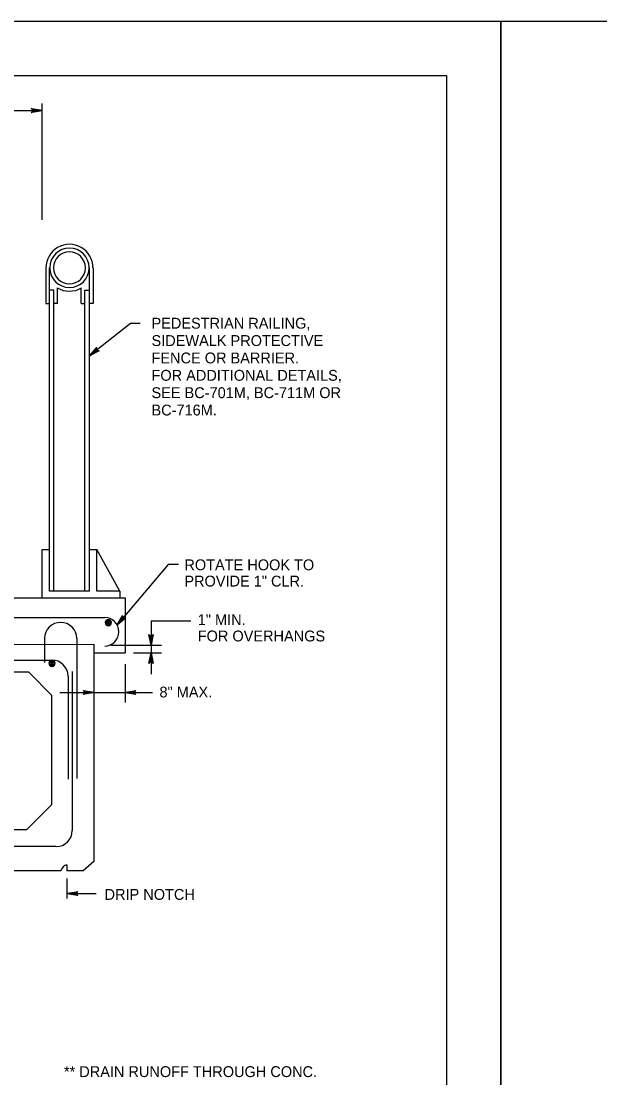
# Model space of a CAD drawing. Extents: x 639331 to 643089, y 299088 to 300975.
# Drawn here: x 642101.4 to 642261.4, y 300577.6 to 300869.7 of the extents above; entities that cross this region are included whole.
import ezdxf

# ---------------------------------------------------------------- set-up
doc = ezdxf.new("R2010")
doc.units = 0
doc.layers.add('1', color=7, linetype='Continuous')
doc.layers.add('PLT-BNDY', color=7, linetype='Continuous')

msp = doc.modelspace()

# ---------------------------------------------------------------- linework, layer by layer
at = {"layer": '1'}
for p, q in [((641433.06, 300854.66), (642219.06, 300854.66)), ((642219.06, 300854.66), (642219.06, 300290.66)), ((642107.24, 300814.74), (642107.24, 300846.94)), ((641973.91, 300844.92), (642107.24, 300844.92)), ((642108.26, 300801.46), (642108.26, 300791.65)), ((642109.28, 300712.15), (642109.28, 300801.46)), ((642120.32, 300712.15), (642120.32, 300801.46)), ((642121.34, 300801.46), (642121.34, 300791.65)), ((642110.51, 300795.33), (642109.28, 300795.33)), ((642110.51, 300712.15), (642110.51, 300795.33)), ((642111.53, 300791.65), (642111.53, 300795.95)), ((642118.07, 300791.65), (642118.07, 300795.95)), ((642119.09, 300795.33), (642120.12, 300795.33)), ((642119.09, 300712.15), (642119.09, 300795.33)), ((642108.26, 300791.65), (642109.28, 300791.65)), ((642111.53, 300791.65), (642110.51, 300791.65)), ((642118.07, 300791.65), (642119.09, 300791.65)), ((642121.34, 300791.65), (642120.32, 300791.65)), ((642131.72, 300786.07), (642120.32, 300777.19)), ((642134.31, 300786.07), (642131.72, 300786.07)), ((642107.24, 300710.31), (642107.24, 300723.6)), ((642107.24, 300723.6), (642109.28, 300723.6)), ((642120.32, 300723.6), (642122.36, 300723.6)), ((642128.7, 300712.15), (642122.36, 300723.6)), ((642122.36, 300712.15), (642122.36, 300723.6)), ((642142.1, 300719.45), (642127.99, 300702.77)), ((642144.97, 300719.45), (642142.1, 300719.45)), ((641973.91, 300710.31), (642130.2, 300710.31)), ((642107.24, 300712.15), (642107.24, 300712.15)), ((642109.28, 300712.15), (642109.28, 300712.15)), ((642120.32, 300712.15), (642109.28, 300712.15)), ((642128.7, 300712.15), (642122.36, 300712.15)), ((642128.7, 300712.15), (642122.36, 300712.15)), ((642128.7, 300712.15), (642128.7, 300710.31)), ((642130.2, 300710.31), (642130.2, 300695.12)), ((641894.89, 300704.84), (642124.52, 300704.84)), ((642137.35, 300703.88), (642137.35, 300697.19)), ((642137.35, 300703.88), (642148.38, 300703.88)), ((642107.92, 300699.03), (642107.91, 300692.42)), ((642116.83, 300699.03), (642116.83, 300660.32)), ((642011.2, 300697.32), (642121.58, 300697.43)), ((642121.58, 300697.43), (642121.58, 300637.44)), ((642121.58, 300695.11), (642130.2, 300695.12)), ((642126.27, 300697.19), (642140.28, 300697.19)), ((642132.51, 300695.12), (642140.28, 300695.12)), ((642137.35, 300697.19), (642137.35, 300695.12)), ((642137.35, 300695.12), (642137.35, 300689.18)), ((642021.7, 300693.08), (642109.95, 300693.08)), ((642110.4, 300692.17), (642110.4, 300692.17)), ((642103.57, 300689.69), (642028.08, 300689.69)), ((642109.95, 300683.32), (642103.57, 300689.69)), ((642115.58, 300689.94), (642115.58, 300645.94)), ((642130.2, 300691.94), (642130.2, 300681.38)), ((642114.41, 300688.62), (642114.41, 300660.19)), ((642112.12, 300684.11), (642121.58, 300684.11)), ((642121.58, 300684.11), (642130.2, 300684.11)), ((642130.2, 300684.11), (642137.74, 300684.11)), ((642109.95, 300653.19), (642109.95, 300683.32)), ((642109.95, 300653.19), (642102.95, 300646.19)), ((642102.95, 300646.19), (642028.83, 300646.19)), ((642111.08, 300641.57), (642020.58, 300641.57)), ((642121.58, 300637.44), (642118.58, 300634.82)), ((642112.45, 300634.82), (642013.2, 300634.82)), ((642114.08, 300636.44), (642114.08, 300634.82)), ((642118.58, 300634.82), (642114.08, 300634.82)), ((642114.12, 300632.75), (642114.12, 300627.18)), ((642114.12, 300628.54), (642122.2, 300628.54))]:
    msp.add_line(p, q, dxfattribs=at)
for points in [[(642107.24, 300844.92), (642104.26, 300844.37), (642104.37, 300844.44), (642104.49, 300844.52), (642104.55, 300844.62), (642104.61, 300844.72), (642104.62, 300844.82), (642104.64, 300844.92), (642104.62, 300845.02), (642104.61, 300845.12), (642104.55, 300845.22), (642104.49, 300845.32), (642104.37, 300845.4), (642104.26, 300845.48), (642107.24, 300844.92), (642104.37, 300845.4), (642104.49, 300845.32), (642107.24, 300844.92), (642104.55, 300845.22), (642104.61, 300845.12), (642107.24, 300844.92), (642104.62, 300845.02), (642104.64, 300844.92), (642107.24, 300844.92), (642104.62, 300844.82), (642104.61, 300844.72), (642107.24, 300844.92), (642104.55, 300844.62), (642104.49, 300844.52), (642107.24, 300844.92), (642104.37, 300844.44)], [(642120.32, 300777.19), (642122.33, 300779.47), (642122.29, 300779.33), (642122.25, 300779.2), (642122.26, 300779.09), (642122.28, 300778.97), (642122.32, 300778.88), (642122.37, 300778.79), (642122.45, 300778.72), (642122.52, 300778.65), (642122.63, 300778.61), (642122.74, 300778.57), (642122.88, 300778.58), (642123.02, 300778.58), (642120.32, 300777.19), (642122.88, 300778.58), (642122.74, 300778.57), (642120.32, 300777.19), (642122.63, 300778.61), (642122.52, 300778.65), (642120.32, 300777.19), (642122.45, 300778.72), (642122.37, 300778.79), (642120.32, 300777.19), (642122.32, 300778.88), (642122.28, 300778.97), (642120.32, 300777.19), (642122.26, 300779.09), (642122.25, 300779.2), (642120.32, 300777.19), (642122.29, 300779.33)], [(642127.99, 300702.77), (642129.49, 300705.41), (642129.48, 300705.27), (642129.46, 300705.13), (642129.5, 300705.02), (642129.54, 300704.91), (642129.6, 300704.83), (642129.67, 300704.75), (642129.76, 300704.7), (642129.84, 300704.65), (642129.96, 300704.63), (642130.07, 300704.61), (642130.21, 300704.65), (642130.34, 300704.68), (642127.99, 300702.77), (642130.21, 300704.65), (642130.07, 300704.61), (642127.99, 300702.77), (642129.96, 300704.63), (642129.84, 300704.65), (642127.99, 300702.77), (642129.76, 300704.7), (642129.67, 300704.75), (642127.99, 300702.77), (642129.6, 300704.83), (642129.54, 300704.91), (642127.99, 300702.77), (642129.5, 300705.02), (642129.46, 300705.13), (642127.99, 300702.77), (642129.48, 300705.27)], [(642137.35, 300697.19), (642136.79, 300700.17), (642136.87, 300700.06), (642136.95, 300699.94), (642137.05, 300699.89), (642137.15, 300699.83), (642137.25, 300699.81), (642137.35, 300699.79), (642137.45, 300699.81), (642137.55, 300699.83), (642137.65, 300699.89), (642137.75, 300699.94), (642137.83, 300700.06), (642137.91, 300700.17), (642137.35, 300697.19), (642137.83, 300700.06), (642137.75, 300699.94), (642137.35, 300697.19), (642137.65, 300699.89), (642137.55, 300699.83), (642137.35, 300697.19), (642137.45, 300699.81), (642137.35, 300699.79), (642137.35, 300697.19), (642137.25, 300699.81), (642137.15, 300699.83), (642137.35, 300697.19), (642137.05, 300699.89), (642136.95, 300699.94), (642137.35, 300697.19), (642136.87, 300700.06)], [(642137.35, 300695.12), (642137.91, 300692.14), (642137.83, 300692.25), (642137.75, 300692.37), (642137.65, 300692.43), (642137.55, 300692.49), (642137.45, 300692.5), (642137.35, 300692.52), (642137.25, 300692.5), (642137.15, 300692.49), (642137.05, 300692.43), (642136.95, 300692.37), (642136.87, 300692.25), (642136.79, 300692.14), (642137.35, 300695.12), (642136.87, 300692.25), (642136.95, 300692.37), (642137.35, 300695.12), (642137.05, 300692.43), (642137.15, 300692.49), (642137.35, 300695.12), (642137.25, 300692.5), (642137.35, 300692.52), (642137.35, 300695.12), (642137.45, 300692.5), (642137.55, 300692.49), (642137.35, 300695.12), (642137.65, 300692.43), (642137.75, 300692.37), (642137.35, 300695.12), (642137.83, 300692.25)], [(642121.58, 300684.11), (642118.59, 300683.55), (642118.71, 300683.63), (642118.82, 300683.71), (642118.88, 300683.81), (642118.94, 300683.91), (642118.96, 300684.01), (642118.98, 300684.11), (642118.96, 300684.21), (642118.94, 300684.31), (642118.88, 300684.41), (642118.82, 300684.51), (642118.71, 300684.59), (642118.59, 300684.67), (642121.58, 300684.11), (642118.71, 300684.59), (642118.82, 300684.51), (642121.58, 300684.11), (642118.88, 300684.41), (642118.94, 300684.31), (642121.58, 300684.11), (642118.96, 300684.21), (642118.98, 300684.11), (642121.58, 300684.11), (642118.96, 300684.01), (642118.94, 300683.91), (642121.58, 300684.11), (642118.88, 300683.81), (642118.82, 300683.71), (642121.58, 300684.11), (642118.71, 300683.63)], [(642130.2, 300684.11), (642133.18, 300684.67), (642133.07, 300684.59), (642132.95, 300684.51), (642132.89, 300684.41), (642132.84, 300684.31), (642132.82, 300684.21), (642132.8, 300684.11), (642132.82, 300684.01), (642132.84, 300683.91), (642132.89, 300683.81), (642132.95, 300683.71), (642133.07, 300683.63), (642133.18, 300683.55), (642130.2, 300684.11), (642133.07, 300683.63), (642132.95, 300683.71), (642130.2, 300684.11), (642132.89, 300683.81), (642132.84, 300683.91), (642130.2, 300684.11), (642132.82, 300684.01), (642132.8, 300684.11), (642130.2, 300684.11), (642132.82, 300684.21), (642132.84, 300684.31), (642130.2, 300684.11), (642132.89, 300684.41), (642132.95, 300684.51), (642130.2, 300684.11), (642133.07, 300684.59)], [(642114.12, 300628.54), (642117.1, 300629.1), (642116.99, 300629.02), (642116.87, 300628.94), (642116.81, 300628.84), (642116.75, 300628.74), (642116.74, 300628.64), (642116.72, 300628.54), (642116.74, 300628.44), (642116.75, 300628.34), (642116.81, 300628.24), (642116.87, 300628.14), (642116.99, 300628.06), (642117.1, 300627.98), (642114.12, 300628.54), (642116.99, 300628.06), (642116.87, 300628.14), (642114.12, 300628.54), (642116.81, 300628.24), (642116.75, 300628.34), (642114.12, 300628.54), (642116.74, 300628.44), (642116.72, 300628.54), (642114.12, 300628.54), (642116.74, 300628.64), (642116.75, 300628.74), (642114.12, 300628.54), (642116.81, 300628.84), (642116.87, 300628.94), (642114.12, 300628.54), (642116.99, 300629.02)]]:
    msp.add_lwpolyline(points, dxfattribs=at)
for centre, radius, start, end in [((642114.79, 300801.51), 6.49, 359.8169, 180.1831), ((642114.8, 300801.49), 5.45, 0, 180), ((642114.8, 300801.49), 4.41, 0, 180), ((642114.8, 300801.49), 5.45, 180, 0), ((642114.8, 300801.49), 4.41, 180, 0), ((642114.79, 300801.51), 6.49, 238.7471, 301.3782), ((642124.52, 300700.9), 3.94, 270.7157, 90), ((642125.56, 300703.44), 0.861, 0, 180), ((642125.56, 300703.44), 0.614, 0, 180), ((642112.37, 300699.03), 4.46, 90, 180), ((642112.37, 300699.03), 4.46, 0, 90), ((642125.56, 300703.44), 0.861, 180, 0), ((642125.56, 300703.44), 0.614, 180, 0), ((642125.56, 300703.44), 0.336, 0, 180), ((642125.56, 300703.44), 0.336, 180, 0), ((642125.56, 300703.44), 0.17, 0, 180), ((642125.56, 300703.44), 0.17, 180, 0), ((642125.56, 300703.44), 0.0726, 0, 180), ((642125.56, 300703.44), 0.0726, 180, 0), ((642109.95, 300692.2), 0.861, 0, 180), ((642109.95, 300692.2), 0.861, 180, 0), ((642109.95, 300692.2), 0.614, 0, 180), ((642109.95, 300692.2), 0.614, 180, 0), ((642109.95, 300692.2), 0.336, 0, 180), ((642109.95, 300692.2), 0.336, 180, 0), ((642109.95, 300692.2), 0.17, 0, 180), ((642109.95, 300692.2), 0.17, 180, 0), ((642109.95, 300692.2), 0.0726, 0, 180), ((642109.95, 300692.2), 0.0726, 180, 0), ((642109.95, 300688.62), 4.46, 0, 90), ((642111.14, 300645.98), 4.46, 270, 0), ((642114.55, 300634.4), 2.14, 101.5949, 167.5435)]:
    msp.add_arc(centre, radius, start, end, dxfattribs=at)
at = {"layer": 'PLT-BNDY'}
for points in [[(641393.06, 300869.66), (642234.06, 300869.66), (642234.06, 300275.66), (641393.06, 300275.66)], [(642234.06, 300869.66), (643075.06, 300869.66), (643075.06, 300275.66), (642234.06, 300275.66)]]:
    msp.add_lwpolyline(points, close=True, dxfattribs=at)

# ---------------------------------------------------------------- texts
at = {"layer": '1'}
for s, p in [('PEDESTRIAN RAILING,', (642137.49, 300784.67)), ('SIDEWALK PROTECTIVE', (642137.49, 300779.87)), ('FENCE OR BARRIER.', (642137.49, 300775.07)), ('FOR ADDITIONAL DETAILS,', (642137.49, 300770.27)), ('SEE BC-701M, BC-711M OR', (642137.49, 300765.47)), ('BC-716M.', (642137.49, 300760.67)), ('ROTATE HOOK TO', (642146.58, 300717.9)), ('PROVIDE 1" CLR.', (642146.58, 300713.4)), ('1" MIN.', (642150.27, 300702.73)), ('FOR OVERHANGS', (642150.27, 300698.23)), ('8" MAX.', (642139.69, 300682.74)), ('DRIP NOTCH', (642124.51, 300626.81)), ('** DRAIN RUNOFF THROUGH CONC.', (642113.28, 300577.83))]:
    msp.add_text(s, height=3, dxfattribs=at).set_placement(p)

doc.saveas('drawing.dxf')
